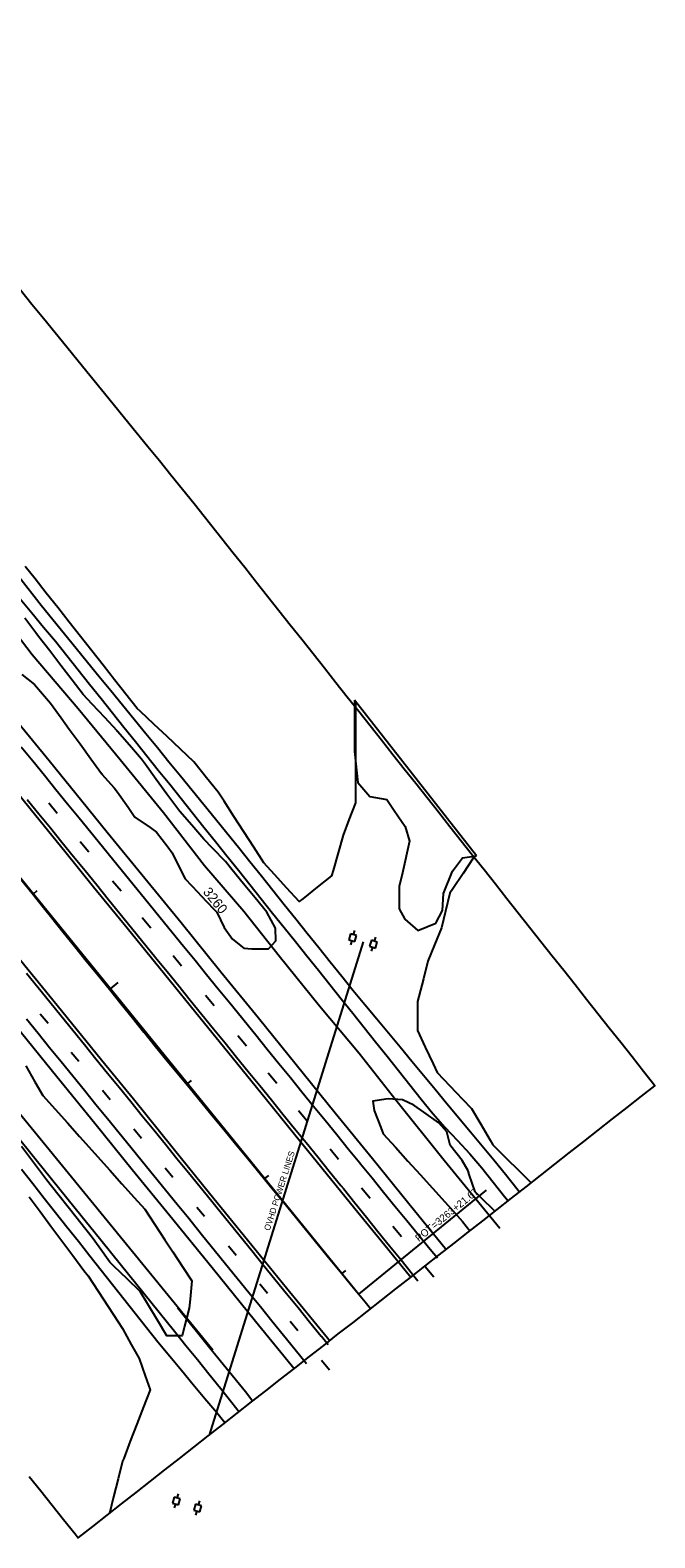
# Model space of a CAD drawing. Extents: x 2132221 to 2141942, y 535736 to 547298.
# Drawn here: x 2141431 to 2141942, y 536027 to 537259 of the extents above; entities that cross this region are included whole.
import ezdxf

# ---------------------------------------------------------------- set-up
doc = ezdxf.new("R2010")
doc.units = 0
for name, color, linetype in [('RD_EX_Driveway', 7, 'Continuous'), ('RD_EX_Fence_ChLk', 7, 'Continuous'), ('RD_EX_Fence_Other', 7, 'Continuous'), ('RD_EX_GuardRail', 7, 'Continuous'), ('RD_EX_H2O', 7, 'Continuous'), ('RD_EX_Misc', 7, 'Continuous'), ('RD_EX_Road', 7, 'Continuous'), ('RD_EX_UT', 7, 'Continuous'), ('RD_EX_UT_txCode', 7, 'Continuous'), ('RD_EX_VEG', 7, 'Continuous'), ('RD_HC_Cl', 7, 'Continuous'), ('RD_HC_Data', 7, 'Continuous'), ('RD_HC_Data_Tic', 7, 'Continuous'), ('RD_HC_TX_Sta50', 7, 'Continuous'), ('TOPO_E_TLIML-Line', 7, 'Continuous')]:
    doc.layers.add(name, color=color, linetype=linetype)

msp = doc.modelspace()

# ---------------------------------------------------------------- linework, layer by layer
at = {"layer": 'RD_EX_Driveway'}
for points in [[(2141830.9, 536310), (2141828.9, 536312.5), (2141819.6, 536324.3), (2141810.1, 536335.9), (2141800.5, 536347.4), (2141790.9, 536358.9), (2141771.8, 536382), (2141762.2, 536393.6), (2141752.6, 536405.1), (2141743, 536416.7), (2141733.4, 536428.2), (2141723.9, 536439.8), (2141714.3, 536451.3), (2141704.7, 536462.9), (2141695.1, 536474.4), (2141685.8, 536486.1), (2141676.4, 536497.8), (2141667, 536509.5), (2141657.6, 536521.2), (2141648.2, 536532.9), (2141638.8, 536544.6), (2141629.4, 536556.3), (2141620, 536567.9), (2141610.6, 536579.6), (2141601.2, 536591.3), (2141591.8, 536603), (2141582.4, 536614.7), (2141573, 536626.4), (2141563.5, 536638), (2141554, 536649.6), (2141544.5, 536661.2), (2141535, 536672.8), (2141525.5, 536684.4), (2141516, 536696.1), (2141506.5, 536707.7), (2141497, 536719.3), (2141487.5, 536730.9), (2141478, 536742.5), (2141468.5, 536754.1), (2141459, 536765.7), (2141449.5, 536777.3), (2141440.1, 536789), (2141421.6, 536812.6)], [(2141422.9, 536794.5), (2141432.4, 536783), (2141442, 536771.4), (2141451.6, 536759.9), (2141460.9, 536748.2), (2141470.3, 536736.6), (2141479.6, 536724.9), (2141489, 536713.2), (2141498.3, 536701.5), (2141507.7, 536689.8), (2141517, 536678.1), (2141526.4, 536666.4), (2141535.7, 536654.7), (2141545.1, 536643.1), (2141554.4, 536631.4), (2141563.8, 536619.7), (2141573.1, 536608), (2141582.5, 536596.3), (2141591.8, 536584.6), (2141601.2, 536572.9), (2141610.5, 536561.2), (2141619.9, 536549.6), (2141629.2, 536537.9), (2141638.6, 536526.2), (2141647.9, 536514.5), (2141657.3, 536502.8), (2141666.7, 536491.1), (2141676, 536479.4), (2141685.4, 536467.7), (2141694.7, 536456.1), (2141704.1, 536444.4), (2141713.4, 536432.7), (2141722.8, 536421), (2141732.1, 536409.3), (2141741.5, 536397.6), (2141750.8, 536385.9), (2141760.2, 536374.2), (2141770.1, 536363), (2141780.3, 536352.1), (2141790.5, 536341.2), (2141800.3, 536329.8), (2141809.6, 536318.1), (2141818.9, 536306.4), (2141821.8, 536302.8)], [(2141417.1, 536359.6), (2141435.9, 536336.3), (2141473.6, 536289.7), (2141483, 536278), (2141511.3, 536243), (2141549, 536196.4), (2141558.4, 536184.7), (2141567.8, 536173.1), (2141577.2, 536161.4), (2141586.6, 536149.8), (2141595.9, 536138.1), (2141601.9, 536130.5)], [(2141590.2, 536121.4), (2141583.5, 536129.5), (2141573.9, 536141), (2141564.3, 536152.6), (2141554.7, 536164.1), (2141545.1, 536175.6), (2141535.5, 536187.2), (2141526.2, 536198.9), (2141516.9, 536210.7), (2141507.6, 536222.5), (2141498.3, 536234.2), (2141489, 536246), (2141479.7, 536257.7), (2141470.4, 536269.5), (2141461.1, 536281.3), (2141451.7, 536293), (2141442.4, 536304.8), (2141433.1, 536316.6), (2141423.8, 536328.3)]]:
    msp.add_lwpolyline(points, dxfattribs=at)
at = {"layer": 'RD_EX_Fence_ChLk'}
msp.add_lwpolyline([(2141551.5, 536215.6), (2141578, 536182.8), (2141607, 536146.9), (2141613, 536139.2)], dxfattribs=at)
at = {"layer": 'RD_EX_Fence_Other'}
for points in [[(2140958.2, 537332.7), (2141227.5, 537003.4), (2141259.3, 536963.9), (2141294.1, 536921.7), (2141333.8, 536872.8), (2141367.7, 536831.9), (2141401, 536790.3), (2141432.6, 536749.1), (2141470.3, 536704.9), (2141504.5, 536663.3), (2141540, 536620), (2141573.5, 536576.7), (2141605.6, 536539.4), (2141634.7, 536502.8), (2141667.6, 536462), (2141700, 536423.3), (2141729.9, 536385.4), (2141769.4, 536336), (2141815, 536280.4)], [(2141580.4, 536180.8), (2141441.6, 536350.4), (2141263.3, 536567.7)]]:
    msp.add_lwpolyline(points, dxfattribs=at)
at = {"layer": 'RD_EX_GuardRail'}
msp.add_lwpolyline([(2141709.3, 536214.6), (2141704.9, 536219.9), (2141695.4, 536231.5), (2141685.9, 536243.1), (2141676.4, 536254.7), (2141666.8, 536266.3), (2141657.3, 536277.9), (2141647.8, 536289.5), (2141638.3, 536301.1), (2141628.8, 536312.7), (2141619.3, 536324.3), (2141609.7, 536335.9), (2141600.2, 536347.5), (2141590.7, 536359.1), (2141581.2, 536370.7), (2141571.7, 536382.3), (2141562.2, 536393.9), (2141552.6, 536405.5), (2141543.1, 536417), (2141533.6, 536428.6), (2141524.1, 536440.2), (2141524, 536440.3), (2141514.6, 536452), (2141505.2, 536463.7), (2141495.8, 536475.4), (2141486.4, 536487), (2141476.9, 536498.7), (2141467.5, 536510.4), (2141458.1, 536522.1), (2141448.7, 536533.7), (2141441.9, 536542.2), (2141432.5, 536553.9), (2141423.1, 536565.6)], dxfattribs=at)
at = {"layer": 'RD_EX_H2O'}
msp.add_line((2141795.8, 536584.5), (2141696.2, 536711.8), dxfattribs=at)
msp.add_lwpolyline([(2141696.2, 536711.8), (2141696.2, 536669.8), (2141699, 536644.6), (2141708.8, 536633.2), (2141722.7, 536630.5), (2141728.7, 536621.7), (2141737.6, 536608.7), (2141741.1, 536596.7), (2141735.3, 536570.8), (2141732.8, 536559.6), (2141732.8, 536541.4), (2141737.3, 536532.8), (2141747.9, 536523.7), (2141762.7, 536529.7), (2141768.1, 536540), (2141769, 536553.8), (2141776.4, 536572.1), (2141784.5, 536582.9), (2141795.8, 536584.5)], dxfattribs=at)
at = {"layer": 'RD_EX_Misc'}
for p, q in [((2141446.2, 536628), (2141453.2, 536619.5)), ((2141472, 536596.3), (2141479, 536587.8)), ((2141498.2, 536564.3), (2141505.3, 536555.9)), ((2141522.6, 536534.2), (2141529.6, 536525.7)), ((2141547.8, 536503.3), (2141554.8, 536494.8)), ((2141574.4, 536470.7), (2141581.4, 536462.3)), ((2141439.3, 536455.5), (2141445.6, 536448)), ((2141600.9, 536437.9), (2141607.9, 536429.5)), ((2141464.5, 536424.3), (2141470.8, 536416.8)), ((2141625.6, 536407.3), (2141632.6, 536398.9)), ((2141490, 536393.1), (2141496.3, 536385.6)), ((2141650.5, 536376.7), (2141657.5, 536368.2)), ((2141515.7, 536361.5), (2141522, 536354)), ((2141676.2, 536345.2), (2141683.2, 536336.7)), ((2141541.4, 536329.8), (2141547.7, 536322.2)), ((2141701.9, 536313.5), (2141708.9, 536305)), ((2141567.3, 536297.7), (2141573.6, 536290.2)), ((2141727.5, 536282), (2141734.5, 536273.6)), ((2141593.2, 536266), (2141599.5, 536258.5)), ((2141754, 536249.2), (2141761, 536240.8)), ((2141618.7, 536234.9), (2141625, 536227.4)), ((2141643.6, 536204.4), (2141649.9, 536196.9)), ((2141669.1, 536172.5), (2141675.6, 536164.6))]:
    msp.add_line(p, q, dxfattribs=at)
for points in [[(2141423.7, 536673.7), (2141433.2, 536662.1), (2141442.7, 536650.5), (2141452.1, 536638.8), (2141461.6, 536627.2), (2141471.1, 536615.6), (2141480.6, 536603.9), (2141490, 536592.3), (2141499.5, 536580.7), (2141509, 536569.1), (2141518.5, 536557.4), (2141527.9, 536545.8), (2141537.4, 536534.2), (2141546.9, 536522.5), (2141556.4, 536510.9), (2141565.8, 536499.3), (2141575.3, 536487.7), (2141584.8, 536476), (2141594.3, 536464.4), (2141603.7, 536452.8), (2141605.9, 536450.1), (2141615.4, 536438.4), (2141624.9, 536426.8), (2141634.3, 536415.1), (2141643.8, 536403.5), (2141653.2, 536391.9), (2141662.7, 536380.2), (2141672.2, 536368.6), (2141681.6, 536356.9), (2141691.1, 536345.3), (2141700.5, 536333.7), (2141701, 536333.1), (2141710.5, 536321.5), (2141720, 536309.8), (2141729.5, 536298.2), (2141739, 536286.6), (2141748.5, 536275), (2141758, 536263.4), (2141763.9, 536256.2)], [(2141428.6, 536630.7), (2141438, 536619), (2141447.5, 536607.4), (2141457, 536595.7), (2141466.4, 536584.1), (2141475.9, 536572.5), (2141485.4, 536560.8), (2141494.8, 536549.2), (2141504.3, 536537.6), (2141513.8, 536525.9), (2141523.2, 536514.3), (2141532.7, 536502.7), (2141533.6, 536501.6), (2141543, 536490), (2141552.5, 536478.3), (2141561.9, 536466.7), (2141571.4, 536455), (2141580.9, 536443.4), (2141590.3, 536431.8), (2141599.8, 536420.1), (2141609.3, 536408.5), (2141618.7, 536396.9), (2141628.2, 536385.2), (2141637.7, 536373.6), (2141647.1, 536361.9), (2141656.6, 536350.3), (2141666.1, 536338.7), (2141675.5, 536327), (2141685, 536315.4), (2141687.1, 536312.8), (2141696.5, 536301.2), (2141705.9, 536289.5), (2141715.3, 536277.8), (2141724.8, 536266.1), (2141734.2, 536254.5), (2141743.6, 536242.8), (2141747.9, 536237.5)], [(2141428, 536488.7), (2141437.5, 536477.1), (2141447, 536465.4), (2141456.4, 536453.8), (2141465.9, 536442.2), (2141475.3, 536430.5), (2141484.8, 536418.9), (2141494.3, 536407.2), (2141503.7, 536395.6), (2141513.2, 536384), (2141522.6, 536372.3), (2141532.1, 536360.7), (2141541.6, 536349), (2141551, 536337.4), (2141560.5, 536325.8), (2141569.9, 536314.1), (2141579.4, 536302.5), (2141583.8, 536297.1), (2141593.3, 536285.4), (2141602.7, 536273.8), (2141612.2, 536262.2), (2141621.6, 536250.5), (2141631.1, 536238.9), (2141640.6, 536227.2), (2141650, 536215.6), (2141659.5, 536204), (2141668.9, 536192.3), (2141669.1, 536192.1), (2141674.6, 536185.4)], [(2141657, 536169.5), (2141647.6, 536181.1), (2141638.1, 536192.8), (2141628.6, 536204.4), (2141619.2, 536216.1), (2141609.7, 536227.7), (2141600.3, 536239.4), (2141590.8, 536251), (2141581.4, 536262.6), (2141571.9, 536274.3), (2141562.5, 536285.9), (2141560.6, 536288.3), (2141551.1, 536299.9), (2141541.6, 536311.5), (2141532.1, 536323.2), (2141522.7, 536334.8), (2141513.2, 536346.4), (2141503.7, 536358.1), (2141494.2, 536369.7), (2141484.8, 536381.3), (2141475.3, 536393), (2141465.8, 536404.6), (2141456.4, 536416.2), (2141446.9, 536427.9), (2141437.4, 536439.5), (2141427.9, 536451.1)]]:
    msp.add_lwpolyline(points, dxfattribs=at)
at = {"layer": 'RD_EX_Road'}
for points in [[(2141400.2, 536719.5), (2141421.7, 536692.8), (2141446.4, 536662.4), (2141473.2, 536629.6), (2141494, 536603.9), (2141524.7, 536566.5), (2141554.5, 536530.1), (2141586.9, 536489.9), (2141617.6, 536452.3), (2141648.4, 536414.2), (2141680.5, 536374.6), (2141710.8, 536337.4), (2141745.2, 536295), (2141770.4, 536264), (2141771.1, 536263.1)], [(2141368, 536700.6), (2141388.1, 536676.1), (2141413.8, 536644.5), (2141435.7, 536617.5), (2141459.3, 536588.5), (2141482.9, 536559.4), (2141510.3, 536525.8), (2141540.7, 536488.3), (2141570.1, 536452.2), (2141596.1, 536420.2), (2141624.1, 536385.6), (2141647.2, 536357.2), (2141669.4, 536329.7), (2141696.5, 536296.5), (2141723.5, 536263.5), (2141742.2, 536240.4)], [(2141216.6, 536694.9), (2141233.5, 536674.3), (2141263, 536638.3), (2141290.3, 536604.5), (2141320.2, 536567.8), (2141351.5, 536529.1), (2141386.2, 536486.3), (2141419.3, 536445.8), (2141452.9, 536404.3), (2141483.8, 536366.1), (2141514.5, 536328.3), (2141545.3, 536290.7), (2141579.9, 536248.3), (2141615.3, 536204.4), (2141646.9, 536165.8)], [(2141307.3, 536642), (2141335.6, 536607.5), (2141366.2, 536569.4), (2141395.1, 536533.5), (2141423.1, 536499.3), (2141453, 536462.6), (2141489.3, 536418.1), (2141515.4, 536386), (2141548, 536345.8), (2141577.5, 536309.1), (2141608.8, 536270.8), (2141640.5, 536231.7), (2141674.1, 536190.8), (2141675.9, 536188.5)]]:
    msp.add_lwpolyline(points, dxfattribs=at)
at = {"layer": 'RD_EX_UT'}
for p, q in [((2141696.1, 536523.5), (2141695.2, 536520.2)), ((2141577.5, 536111.4), (2141703.4, 536514.4)), ((2141692.9, 536520.8), (2141691.6, 536516)), ((2141691.6, 536516), (2141696.4, 536514.7)), ((2141697.7, 536519.5), (2141692.9, 536520.8)), ((2141694, 536515.4), (2141693, 536511.9)), ((2141696.4, 536514.7), (2141697.7, 536519.5)), ((2141710, 536515.6), (2141708.5, 536510.8)), ((2141708.5, 536510.8), (2141713.3, 536509.3)), ((2141714.8, 536514.1), (2141710, 536515.6)), ((2141713.4, 536518.1), (2141712.3, 536514.8)), ((2141713.3, 536509.3), (2141714.8, 536514.1)), ((2141710.8, 536510.1), (2141709.7, 536506.7)), ((2141548.8, 536060.7), (2141547.5, 536055.8)), ((2141547.5, 536055.8), (2141552.3, 536054.5)), ((2141553.6, 536059.4), (2141548.8, 536060.7)), ((2141549.1, 536051.9), (2141550, 536055.2)), ((2141551.2, 536059.9), (2141552.2, 536063.4)), ((2141552.3, 536054.5), (2141553.6, 536059.4)), ((2141566.3, 536054.9), (2141564.9, 536050.1)), ((2141571.1, 536053.5), (2141566.3, 536054.9)), ((2141568.7, 536054.1), (2141569.7, 536057.6)), ((2141564.9, 536050.1), (2141569.7, 536048.7)), ((2141566.4, 536046.1), (2141567.4, 536049.4)), ((2141569.7, 536048.7), (2141571.1, 536053.5))]:
    msp.add_line(p, q, dxfattribs=at)
at = {"layer": 'RD_EX_VEG'}
for points in [[(2141696.9, 536710.5), (2141696.9, 536695.5), (2141696.9, 536680.5), (2141696.9, 536665.5), (2141696.9, 536650.5), (2141696.9, 536635.5), (2141696.9, 536627.9), (2141691.5, 536613.9), (2141686.8, 536601.4), (2141682.7, 536587), (2141678.6, 536572.6), (2141677.4, 536568.3), (2141665.7, 536558.9), (2141654, 536549.6), (2141651, 536547.2), (2141640.9, 536558.3), (2141630.8, 536569.4), (2141622.1, 536579), (2141614, 536591.6), (2141605.8, 536604.2), (2141597.6, 536616.8), (2141589.5, 536629.3), (2141584.7, 536636.7), (2141575.3, 536648.4), (2141565.8, 536660), (2141564.7, 536661.4), (2141553.8, 536671.7), (2141542.9, 536682), (2141532, 536692.2), (2141521.1, 536702.5), (2141518.5, 536704.9), (2141509.2, 536716.7), (2141499.9, 536728.5), (2141490.7, 536740.3), (2141481.4, 536752.1), (2141472.1, 536763.8), (2141462.8, 536775.6), (2141453.5, 536787.4), (2141444.2, 536799.2), (2141435, 536811), (2141427, 536821.1)], [(2141424.2, 536732.7), (2141434.5, 536724.5), (2141444.3, 536713.2), (2141447.6, 536709.4), (2141456.4, 536697.3), (2141463, 536688.2), (2141471.8, 536676), (2141480.6, 536663.9), (2141489.4, 536651.8), (2141489.7, 536651.4), (2141499.6, 536640.1), (2141502.5, 536636.7), (2141511, 536624.4), (2141516.7, 536616.3), (2141529, 536607.7), (2141534.4, 536603.9), (2141543.5, 536592), (2141547.1, 536587.2), (2141553.7, 536573.8), (2141557.6, 536565.9), (2141568, 536555), (2141570.6, 536552.2), (2141581, 536541.4), (2141583.7, 536538.6), (2141589.7, 536526.1), (2141596.4, 536516.5), (2141605.6, 536509.3), (2141612.3, 536508.7), (2141625.8, 536508.7), (2141631.9, 536515.2), (2141631.6, 536525.5), (2141624.4, 536538.5), (2141615, 536550.2), (2141605.5, 536561.8), (2141596, 536573.4), (2141590.6, 536580), (2141580.2, 536590.8), (2141573, 536598.3), (2141563.2, 536609.6), (2141553.4, 536620.9), (2141551.7, 536622.9), (2141542.8, 536635), (2141534, 536647.1), (2141525.2, 536659.2), (2141522.1, 536663.5), (2141512.3, 536674.9), (2141502.5, 536686.2), (2141502.2, 536686.6), (2141492, 536697.5), (2141481.8, 536708.5), (2141474.4, 536716.3), (2141465.3, 536728.2), (2141456.2, 536740.1), (2141447.1, 536752), (2141437.9, 536763.9), (2141435.7, 536766.9), (2141426.6, 536778.8)], [(2141794.8, 536582.3), (2141793.3, 536582.6), (2141785, 536570.1), (2141776.6, 536557.7), (2141774.1, 536554), (2141770.7, 536539.4), (2141767.4, 536525.7), (2141761.7, 536511.8), (2141756.2, 536498.7), (2141752.5, 536484.1), (2141748.7, 536469.6), (2141747.7, 536465.5), (2141747.7, 536450.5), (2141747.7, 536441.8), (2141754, 536428.2), (2141760.4, 536414.6), (2141763.7, 536407.5), (2141774, 536396.7), (2141784.4, 536385.8), (2141791.7, 536378.2), (2141799.4, 536365.3), (2141807.1, 536352.4), (2141809.4, 536348.5), (2141820, 536337.9), (2141830.7, 536327.4), (2141840.6, 536317.6)], [(2141427.5, 536413), (2141434.9, 536400), (2141441.4, 536388.7), (2141451.4, 536377.6), (2141461.4, 536366.4), (2141471.4, 536355.2), (2141481.5, 536344.1), (2141486, 536339), (2141496, 536327.8), (2141506, 536316.7), (2141516, 536305.5), (2141524.7, 536295.9), (2141532.9, 536283.4), (2141541.2, 536270.9), (2141547.7, 536261), (2141555.9, 536248.5), (2141563.3, 536237.3), (2141561.8, 536222.4), (2141561, 536215)], [(2141811, 536294.4), (2141810.6, 536294.7), (2141799.8, 536305.1), (2141794.7, 536310.1), (2141790, 536324.4), (2141789.1, 536327.2), (2141784.3, 536335.6), (2141775, 536347.4), (2141774.3, 536348.3), (2141771.6, 536359.1), (2141765.2, 536366.5), (2141752.9, 536375.1), (2141744.8, 536380.8), (2141735.3, 536385.4), (2141723.7, 536386.2), (2141711.2, 536384.3), (2141712.3, 536376.7), (2141717.7, 536362.7), (2141719.7, 536357.6), (2141729.8, 536346.5), (2141739.8, 536335.3), (2141749.9, 536324.2), (2141759.9, 536313.1), (2141770, 536301.9), (2141780, 536290.8), (2141784.6, 536285.8), (2141790.4, 536278.2)], [(2141561, 536215), (2141557.3, 536200.5), (2141555.2, 536192.5), (2141542.7, 536192.5), (2141535, 536205.4), (2141527.2, 536218.3), (2141521, 536228.6), (2141510.2, 536239), (2141499.4, 536249.4), (2141496, 536252.7), (2141487.3, 536265), (2141481.8, 536272.9), (2141472.4, 536284.6), (2141463.1, 536296.3), (2141453.7, 536308.1), (2141444.4, 536319.8), (2141441.8, 536323.1), (2141432.9, 536335.2), (2141424, 536347.3)], [(2141430.1, 536306.1), (2141439.1, 536294), (2141448, 536282), (2141457, 536270), (2141466, 536258), (2141475, 536246), (2141478.4, 536241.6), (2141486.5, 536229), (2141494.7, 536216.4), (2141502.9, 536203.9), (2141506.4, 536198.5), (2141513.7, 536185.4), (2141520.1, 536173.9), (2141525, 536159.8), (2141529, 536148.4), (2141523.6, 536134.4), (2141518.2, 536120.4), (2141512.8, 536106.4), (2141507.5, 536092.4), (2141506.6, 536090.1), (2141502.9, 536075.6), (2141499.2, 536061), (2141495.8, 536047.4)]]:
    msp.add_lwpolyline(points, dxfattribs=at)
at = {"layer": 'RD_HC_Cl'}
msp.add_line((2136971.6, 542041.7), (2141699.6, 536226.5), dxfattribs=at)
at = {"layer": 'RD_HC_Data'}
msp.add_line((2141699.6, 536226.5), (2141804.2, 536311.5), dxfattribs=at)
at = {"layer": 'RD_HC_Data_Tic'}
for p, q in [((2141433.6, 536553.6), (2141436.7, 536556.2)), ((2141496.7, 536476), (2141502.9, 536481.1)), ((2141559.8, 536398.5), (2141562.9, 536401)), ((2141622.9, 536320.9), (2141626, 536323.4)), ((2141686, 536243.3), (2141689.1, 536245.8))]:
    msp.add_line(p, q, dxfattribs=at)
at = {"layer": 'TOPO_E_TLIML-Line'}
msp.add_lwpolyline([(2141430.2, 536077.7), (2141439.6, 536066), (2141448.9, 536054.2), (2141458.3, 536042.5), (2141467.7, 536030.8), (2141470.3, 536027.5), (2141482.1, 536036.7), (2141494, 536046), (2141505.8, 536055.2), (2141517.6, 536064.5), (2141529.4, 536073.7), (2141541.2, 536083), (2141553, 536092.2), (2141564.8, 536101.5), (2141576.6, 536110.7), (2141588.4, 536120), (2141600.2, 536129.2), (2141612, 536138.5), (2141623.8, 536147.7), (2141635.6, 536157), (2141647.5, 536166.2), (2141659.3, 536175.5), (2141671.1, 536184.7), (2141682.9, 536194), (2141694.7, 536203.2), (2141706.5, 536212.5), (2141718.3, 536221.7), (2141730.1, 536231), (2141741.9, 536240.2), (2141753.7, 536249.5), (2141765.5, 536258.7), (2141777.3, 536268), (2141789.2, 536277.2), (2141801, 536286.5), (2141812.8, 536295.7), (2141824.6, 536305), (2141836.4, 536314.2), (2141848.2, 536323.5), (2141860, 536332.7), (2141871.8, 536342), (2141883.6, 536351.2), (2141895.4, 536360.5), (2141907.2, 536369.7), (2141919, 536379), (2141930.8, 536388.2), (2141941.8, 536396.8), (2141932.5, 536408.5), (2141923.1, 536420.3), (2141913.8, 536432.1), (2141904.5, 536443.8), (2141895.2, 536455.6), (2141885.9, 536467.3), (2141876.6, 536479.1), (2141867.3, 536490.9), (2141857.9, 536502.6), (2141848.6, 536514.4), (2141839.3, 536526.1), (2141830, 536537.9), (2141820.7, 536549.6), (2141811.4, 536561.4), (2141802.1, 536573.2), (2141792.7, 536584.9), (2141783.4, 536596.7), (2141774.1, 536608.4), (2141764.8, 536620.2), (2141755.5, 536632), (2141746.2, 536643.7), (2141736.9, 536655.5), (2141727.5, 536667.2), (2141718.2, 536679), (2141708.9, 536690.7), (2141699.6, 536702.5), (2141690.3, 536714.3), (2141681, 536726), (2141671.7, 536737.8), (2141662.3, 536749.5), (2141653, 536761.3), (2141643.7, 536773), (2141634.4, 536784.8), (2141625.1, 536796.6), (2141615.8, 536808.3), (2141606.5, 536820.1), (2141597.1, 536831.8), (2141587.8, 536843.6), (2141578.5, 536855.4), (2141569.2, 536867.1), (2141565.1, 536872.3), (2141555.6, 536883.9), (2141546.1, 536895.6), (2141536.7, 536907.2), (2141527.2, 536918.8), (2141517.7, 536930.4), (2141508.2, 536942.1), (2141498.8, 536953.7), (2141489.3, 536965.3), (2141479.8, 536977), (2141470.3, 536988.6), (2141460.9, 537000.2), (2141451.4, 537011.8), (2141441.9, 537023.5), (2141432.4, 537035.1), (2141423, 537046.7)], dxfattribs=at)

# ---------------------------------------------------------------- texts
at = {"layer": 'RD_EX_UT_txCode'}
msp.add_text('OVHD POWER LINES', height=5, rotation=72.1784, dxfattribs=at).set_placement((2141626.8, 536278))
at = {"layer": 'RD_HC_Data'}
msp.add_text('POT=3263+21.67', height=6, rotation=39.1127, dxfattribs=at).set_placement((2141748.8, 536269))
at = {"layer": 'RD_HC_TX_Sta50'}
msp.add_text('3260', height=8, rotation=309.1127, dxfattribs=at).set_placement((2141571.8, 536554.9))

doc.saveas('drawing.dxf')
